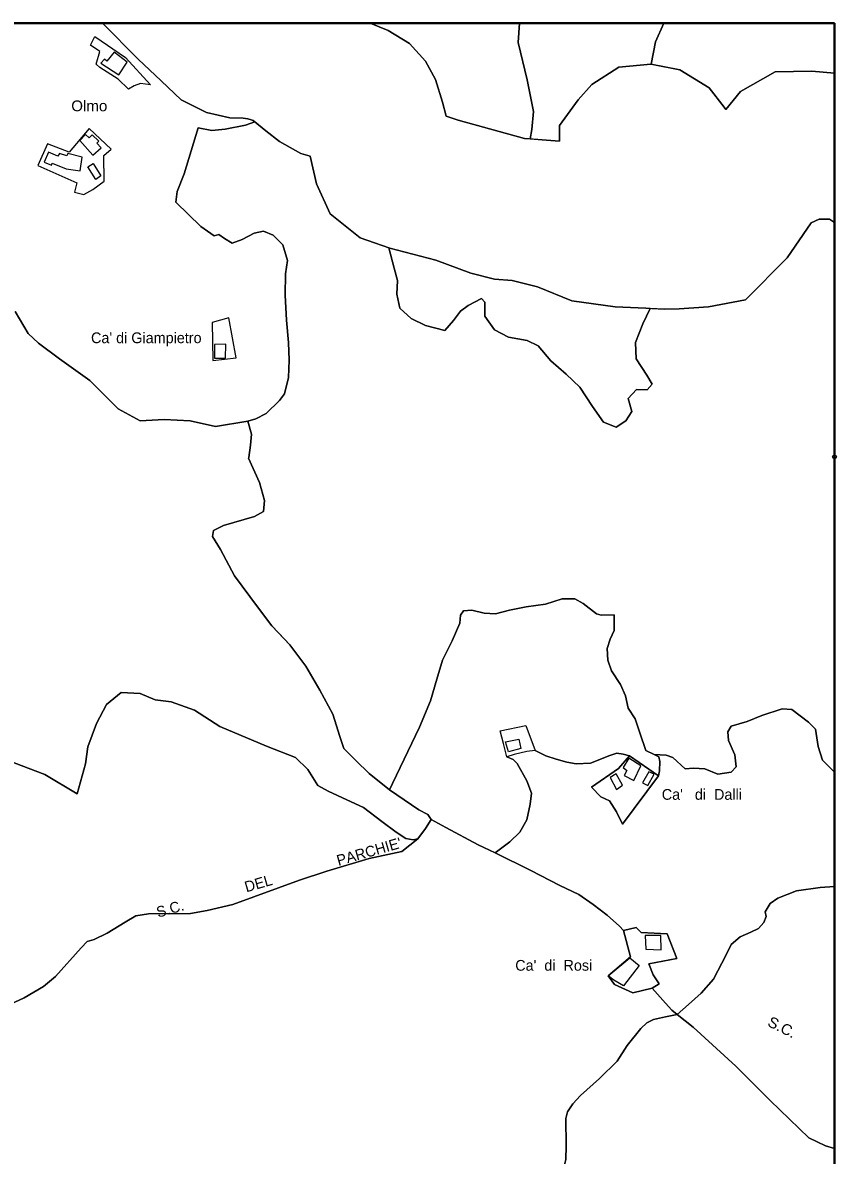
# Model space of a CAD drawing. Extents: x 650071 to 653841, y 889105 to 891996.
# Drawn here: x 653235 to 653841, y 891152 to 891996 of the extents above; entities that cross this region are included whole.
import ezdxf
from ezdxf.enums import TextEntityAlignment as Align

# ---------------------------------------------------------------- set-up
doc = ezdxf.new("R2010")
doc.units = 0
doc.header["$LTSCALE"] = 5.6
doc.header["$PDMODE"] = 32
doc.header["$PDSIZE"] = 2.8
for name, color, linetype, lineweight in [('2', 7, 'Continuous', 25), ('3', 7, 'Continuous', 25), ('36', 7, 'Continuous', 25), ('37', 7, 'Continuous', 25), ('4', 7, 'Continuous', 25), ('55', 7, 'Continuous', 25), ('61', 7, 'Continuous', 35)]:
    doc.layers.add(name, color=color, linetype=linetype, lineweight=lineweight)
doc.layers.add('60', color=7, linetype='Continuous')

msp = doc.modelspace()

# ---------------------------------------------------------------- linework, layer by layer
at = {"layer": '2'}
for points in [[(653330.45, 891949.72), (653322.99, 891950.77), (653318.29, 891949.07), (653314.09, 891946.47), (653306.31, 891953.92), (653292.79, 891962.67), (653290.09, 891965.17), (653292.79, 891974.67), (653285.68, 891979.43), (653289.08, 891985.9), (653311.75, 891970.13)], [(653296.11, 891968.89), (653293.5, 891965.94), (653306.88, 891957.2), (653313, 891966.62), (653303.36, 891974.1), (653298.04, 891967.41)], [(653253.81, 891905.82), (653246.6, 891889.79), (653275.59, 891876.74), (653273.87, 891869.94), (653280.67, 891868.22), (653287.44, 891871.96), (653295.82, 891878.11), (653295.61, 891897.11), (653301.13, 891902), (653284.79, 891917.28), (653269.94, 891899.66)], [(653277.82, 891908.39), (653287.49, 891897.46), (653293.63, 891902.88), (653290.52, 891906.38), (653292.02, 891907.88), (653286.97, 891912.52), (653284.65, 891910.33), (653282.06, 891912.79)], [(653254.37, 891899.55), (653251.37, 891892.18), (653256.61, 891889.88), (653257.19, 891891.34), (653267.71, 891887.14), (653278, 891885.65), (653279.49, 891895.94), (653268.83, 891898.73), (653268.01, 891896.82), (653262.6, 891898.74), (653261.47, 891896.55)], [(653283.7, 891888.77), (653287.79, 891891.09), (653293.38, 891882.04), (653289.7, 891879.22)]]:
    msp.add_lwpolyline(points, close=True, dxfattribs=at)
at = {"layer": '3'}
for points in [[(653682.6, 891319.93), (653687.83, 891300.33), (653671.37, 891286.21), (653676.04, 891279.79), (653689.53, 891273.61), (653703.92, 891277.04), (653709.26, 891280.11), (653704.85, 891286.88), (653701.65, 891295.12), (653722.31, 891299.02), (653715.14, 891317.55), (653695.92, 891318.37)], [(653695.92, 891318.37), (653692.01, 891322.29), (653682.6, 891319.93)]]:
    msp.add_lwpolyline(points, dxfattribs=at)
for points in [[(653698.85, 891316.3), (653699.41, 891306.08), (653710.76, 891305.52), (653710.55, 891316.28)], [(653687.3, 891299.55), (653694.35, 891293.8), (653682.6, 891278.64), (653675.55, 891283.08), (653671.37, 891286.21)]]:
    msp.add_lwpolyline(points, close=True, dxfattribs=at)
at = {"layer": '36'}
msp.add_line((653839.8, 891672.75), (653839.8, 891847.21), dxfattribs=at)
for points in [[(653635.09, 891907.74), (653635.09, 891919.48), (653648.99, 891938.74), (653659.02, 891950.02), (653679.3, 891962.85), (653703.06, 891965.22), (653703.36, 891965.16), (653706.62, 891981.91), (653712.77, 891995.66), (653605.2, 891995.66), (653604.37, 891981.36), (653610.85, 891953.6), (653615.71, 891930.03), (653614.41, 891916.49), (653613.09, 891909.5)], [(653486.68, 891835.79), (653464.3, 891853.71), (653454.16, 891876.01), (653449.23, 891896.62), (653442.41, 891898.73), (653426.57, 891907.6), (653416.27, 891915.57), (653408.04, 891922.15), (653401.11, 891919.7), (653386.07, 891916.68), (653376.21, 891915.68), (653365.84, 891917.69), (653355.47, 891883.48), (653350.29, 891870.39), (653349.25, 891862.34), (653367.92, 891844.23), (653377.75, 891837.41), (653381.38, 891838.42), (653385.53, 891835.4), (653391.29, 891831.94), (653398.82, 891834.59), (653407.56, 891839.27), (653414.48, 891840.9), (653421.83, 891837.91), (653429.04, 891830.75), (653432.57, 891818.88), (653430.97, 891808.93), (653430.65, 891793.14), (653431.68, 891774.52), (653433.24, 891757.92), (653433.76, 891744.83), (653433.24, 891731.75), (653430.13, 891719.68), (653426.5, 891714.65), (653416.65, 891705.09), (653408.87, 891701.06), (653402.99, 891699.2)], [(653613.09, 891909.5), (653622.15, 891908.91), (653635.09, 891907.74)], [(653839.8, 891847.21), (653836.07, 891849.78), (653828.33, 891849.8), (653822.45, 891846.94), (653804.61, 891820.85), (653773.64, 891789.59), (653746.05, 891784.44)], [(653746.05, 891784.44), (653724.27, 891782.85), (653712.92, 891782.78), (653702.45, 891783.21), (653697.11, 891771.88), (653691.73, 891757.95), (653692.23, 891745.82), (653700.17, 891733.6), (653704.12, 891726.81), (653700.21, 891722.54), (653692.43, 891723.01), (653686.12, 891716.29), (653688.98, 891706.52), (653684.5, 891699.59), (653677.17, 891694.91), (653667.88, 891698.58), (653659.58, 891710.15), (653650.24, 891724.74), (653639.93, 891734.42), (653628.46, 891744.36), (653619.13, 891755.43), (653610.99, 891759.31), (653596.99, 891761.82), (653586.62, 891767.36), (653579.36, 891777.42), (653579.36, 891787.98), (653577.06, 891790.6), (653566.91, 891785.47), (653561.19, 891781.24), (653556.02, 891774.4), (653549.59, 891766.78), (653535.14, 891770.65), (653524.56, 891775.74), (653516.22, 891783.48), (653513.98, 891793.86), (653514.39, 891804.04), (653511.94, 891813.21), (653507.87, 891828.28), (653507.86, 891828.35), (653486.68, 891835.79)], [(653415.46, 891640.27), (653411.72, 891653.73), (653403.5, 891671.68), (653403.59, 891672.24), (653405, 891681.4), (653405.75, 891689.62), (653402.99, 891699.2), (653378.9, 891695.4), (653359.98, 891699.6), (653340.51, 891700.65), (653322.67, 891699.6), (653306.46, 891708.51), (653285.37, 891729.49), (653262.67, 891745.75), (653246.99, 891757.28), (653239.42, 891764.63), (653229.69, 891780.88)], [(653402.99, 891699.2), (653405.75, 891689.62), (653405, 891681.4), (653403.59, 891672.24), (653403.5, 891671.68)], [(653728.68, 891440.33), (653734.9, 891440.84), (653743.2, 891440.33), (653753.05, 891436.31), (653762.91, 891437.82), (653766.49, 891441.82), (653765.5, 891450.9), (653760.83, 891461.47), (653760.31, 891468.01), (653762.91, 891472.03), (653774.83, 891475.55), (653785.72, 891480.08), (653800.76, 891485.11), (653808.02, 891484.61), (653820.47, 891475.05), (653825.65, 891470.02), (653827.73, 891456.94), (653830.84, 891446.88), (653839.8, 891437.91), (653839.8, 891672.75)], [(653403.5, 891671.68), (653411.72, 891653.73), (653415.46, 891640.27)], [(653407.99, 891628.31), (653414.71, 891632.05), (653415.46, 891640.27)], [(653415.46, 891640.27), (653414.71, 891632.05), (653407.99, 891628.31)], [(653407.99, 891628.31), (653384.82, 891621.58), (653377.35, 891617.84), (653376.6, 891613.35)], [(653377.35, 891617.84), (653384.82, 891621.58), (653407.99, 891628.31)], [(653410.23, 891561.01), (653393.04, 891584.19), (653382.58, 891603.63), (653376.6, 891613.35), (653377.35, 891617.84)], [(653376.6, 891613.35), (653382.58, 891603.63), (653393.04, 891584.19), (653410.23, 891561.01)], [(653474.49, 891455.58), (653483.45, 891446.61), (653493.17, 891436.89), (653508.52, 891424.77), (653510.59, 891429.39), (653530.78, 891471.39), (653539.08, 891491.01), (653543.75, 891507.11), (653547.9, 891521.2), (653555.16, 891535.79), (653560.86, 891548.87), (653561.38, 891554.91), (653563.45, 891557.93), (653569.68, 891558.43), (653579.01, 891556.42), (653587.31, 891555.92), (653597.68, 891558.43), (653610.12, 891560.95), (653624.64, 891562.96), (653637.09, 891566.99), (653646.42, 891566.99), (653652.65, 891563.47), (653662.5, 891555.92), (653666.13, 891554.91), (653675.79, 891555.05), (653675.79, 891543.48), (653672.68, 891536.94), (653670.6, 891529.89), (653671.12, 891521.34), (653673.71, 891513.29), (653680.45, 891503.23), (653684.08, 891494.67), (653686.16, 891485.62), (653691.34, 891477.57), (653694.86, 891467.21), (653699.34, 891454.02), (653705.56, 891451.03), (653714.51, 891450.53), (653719.35, 891448.89), (653728.68, 891440.33)], [(653446.09, 891516.9), (653434.14, 891532.6), (653420.69, 891546.81), (653410.23, 891561.01)], [(653410.23, 891561.01), (653420.69, 891546.81), (653430.38, 891536.57)], [(653430.38, 891536.57), (653434.14, 891532.6), (653446.09, 891516.9), (653456.55, 891498.95), (653466.27, 891481.01), (653471.5, 891464.56), (653474.49, 891455.58)], [(653466.27, 891481.01), (653456.55, 891498.95), (653446.09, 891516.9)], [(653218.3, 891448.84), (653251.82, 891436.25), (653275.87, 891421.67), (653282.09, 891444.13), (653283.71, 891456.71), (653290.2, 891474.02), (653297.77, 891488.18), (653308.58, 891497.09), (653322.64, 891496.57), (653333.99, 891491.85), (653345.89, 891490.28), (653363.19, 891483.98), (653382.11, 891471.92), (653416.71, 891457.24), (653438.34, 891448.85), (653447.53, 891439.93), (653455.09, 891427.87), (653462.66, 891423.67), (653476.72, 891417.38), (653489.15, 891411.61), (653502.67, 891401.12), (653513.48, 891393.25), (653520.51, 891388.53), (653526.16, 891387.38), (653529.61, 891388.13), (653535.33, 891396), (653539.36, 891402.53), (653536.86, 891406.42), (653530.33, 891409.76), (653508.52, 891424.77)], [(653474.49, 891455.58), (653471.5, 891464.56), (653466.27, 891481.01)], [(653508.52, 891424.77), (653493.17, 891436.89), (653483.45, 891446.61), (653474.49, 891455.58)]]:
    msp.add_lwpolyline(points, dxfattribs=at)
msp.add_lwpolyline([(653766.24, 891218.93), (653791.87, 891193.27), (653820.79, 891165.63), (653833.1, 891159.64), (653839.8, 891157.64), (653839.8, 891352.62), (653829.27, 891352.02), (653811.64, 891349.5), (653797.63, 891343.97), (653791.93, 891339.94), (653788.3, 891333.9), (653788.82, 891330.38), (653787.26, 891325.85), (653783.11, 891321.33), (653777.41, 891318.81), (653769.63, 891315.29), (653762.79, 891309.47), (653759.16, 891301.92), (653749.83, 891283.81), (653740.49, 891273.24), (653730.98, 891264.89), (653722.68, 891257.28), (653734.69, 891247.89)], close=True, dxfattribs=at)
msp.add_point((653839.8, 891672.75), dxfattribs=at)
at = {"layer": '37'}
msp.add_line((653714.51, 891450.53), (653705.56, 891451.03), dxfattribs=at)
for points in [[(653294.78, 891995.66), (653294.8, 891995.96), (653024.92, 891996.11)], [(653408.04, 891922.15), (653406.81, 891923.13), (653405.32, 891923.78), (653402.91, 891924.4), (653399.55, 891924.9), (653389.62, 891925.3), (653372.19, 891929.26), (653353.27, 891938.72), (653338.29, 891952.71), (653321.16, 891968.83), (653294.78, 891995.66)], [(653608.88, 891909.77), (653613.09, 891909.5), (653614.41, 891916.49), (653615.71, 891930.03), (653610.85, 891953.6), (653604.37, 891981.36), (653605.2, 891995.66), (653494, 891995.66)], [(653494, 891995.66), (653507.54, 891990.37), (653523.21, 891980.49), (653535.35, 891967.48), (653542.65, 891953.68), (653547.94, 891936.81), (653550.75, 891926.57), (653559.65, 891923.44), (653608.88, 891909.77)], [(653839.8, 891958.58), (653839.81, 891995.66), (653712.77, 891995.66), (653706.62, 891981.91), (653703.36, 891965.16)], [(653703.36, 891965.16), (653724.73, 891960.89), (653746.57, 891947.62)], [(653746.57, 891947.62), (653757.69, 891933.22), (653758.82, 891931.41), (653769.72, 891944.73), (653795.71, 891959.47), (653823.03, 891959.98), (653839.8, 891958.58)], [(653350.29, 891870.39), (653355.47, 891883.48), (653365.84, 891917.69), (653376.21, 891915.68), (653386.07, 891916.68), (653401.11, 891919.7), (653408.04, 891922.15)], [(653229.69, 891780.88), (653239.42, 891764.63), (653246.99, 891757.28), (653262.67, 891745.75), (653285.37, 891729.49), (653306.46, 891708.51), (653322.67, 891699.6), (653340.51, 891700.65), (653359.98, 891699.6), (653378.9, 891695.4), (653402.99, 891699.2), (653408.87, 891701.06), (653416.65, 891705.09), (653426.5, 891714.65), (653430.13, 891719.68), (653433.24, 891731.75), (653433.76, 891744.83), (653433.24, 891757.92), (653431.68, 891774.52), (653430.65, 891793.14), (653430.97, 891808.93), (653432.57, 891818.88), (653429.04, 891830.75), (653421.83, 891837.91), (653414.48, 891840.9), (653407.56, 891839.27), (653398.82, 891834.59), (653391.29, 891831.94), (653385.53, 891835.4), (653381.38, 891838.42), (653377.75, 891837.41), (653367.92, 891844.23), (653349.25, 891862.34), (653350.29, 891870.39)], [(653507.87, 891828.28), (653511.94, 891813.21), (653514.39, 891804.04), (653513.98, 891793.86), (653516.22, 891783.48), (653524.56, 891775.74), (653535.14, 891770.65), (653549.59, 891766.78), (653556.02, 891774.4), (653561.19, 891781.24), (653566.91, 891785.47), (653577.06, 891790.6), (653579.36, 891787.98), (653579.36, 891777.42), (653586.62, 891767.36), (653596.99, 891761.82), (653610.99, 891759.31), (653619.13, 891755.43), (653628.46, 891744.36), (653639.93, 891734.42), (653650.24, 891724.74)], [(653599.77, 891804), (653586.63, 891804.97), (653569.03, 891809.63), (653542.86, 891819.2), (653508.56, 891828.1), (653507.89, 891828.34)], [(653702.45, 891783.21), (653699.3, 891783.35), (653676.6, 891784.48), (653644.25, 891789.02), (653618.72, 891799.25), (653599.77, 891804)], [(653650.24, 891724.74), (653659.58, 891710.15), (653667.88, 891698.58), (653677.17, 891694.91), (653684.5, 891699.59), (653688.98, 891706.52), (653686.12, 891716.29), (653692.43, 891723.01), (653700.21, 891722.54), (653704.12, 891726.81), (653700.17, 891733.6), (653692.23, 891745.82), (653691.73, 891757.95), (653697.11, 891771.88), (653702.45, 891783.21)], [(653708.81, 891435.22), (653709.6, 891438.85), (653709.82, 891445.85), (653708.95, 891449.35), (653705.56, 891451.03), (653699.34, 891454.02), (653694.86, 891467.21), (653691.34, 891477.57), (653686.16, 891485.62), (653684.08, 891494.67), (653680.45, 891503.23), (653673.71, 891513.29), (653671.12, 891521.34), (653670.6, 891529.89), (653672.68, 891536.94), (653675.79, 891543.48), (653675.79, 891555.05), (653666.13, 891554.91), (653662.5, 891555.92), (653652.65, 891563.47), (653646.42, 891566.99), (653637.09, 891566.99), (653624.64, 891562.96), (653610.12, 891560.95), (653597.68, 891558.43), (653587.31, 891555.92), (653579.01, 891556.42), (653569.68, 891558.43), (653563.45, 891557.93), (653561.38, 891554.91), (653560.86, 891548.87), (653555.16, 891535.79), (653547.9, 891521.2), (653543.75, 891507.11), (653539.08, 891491.01), (653530.78, 891471.39), (653510.59, 891429.39), (653508.52, 891424.77), (653530.33, 891409.76)], [(653278.74, 891306.98), (653283.17, 891311.85), (653288.49, 891313.18), (653298.24, 891318.06), (653311.54, 891326.05), (653319.52, 891330.92), (653328.83, 891332.25), (653360.29, 891332.7), (653372.7, 891334.92), (653391.76, 891339.35), (653441.41, 891357.53), (653461.8, 891364.18), (653493.27, 891373.49), (653517.64, 891378.82), (653529.61, 891388.13), (653526.16, 891387.38), (653520.51, 891388.53), (653513.48, 891393.25), (653502.67, 891401.12), (653489.15, 891411.61), (653476.72, 891417.38), (653462.66, 891423.67), (653455.09, 891427.87), (653447.53, 891439.93), (653438.34, 891448.85), (653416.71, 891457.24), (653382.11, 891471.92), (653363.19, 891483.98), (653345.89, 891490.28), (653333.99, 891491.85), (653322.64, 891496.57), (653308.58, 891497.09), (653297.77, 891488.18), (653290.2, 891474.02), (653283.71, 891456.71), (653282.09, 891444.13), (653275.87, 891421.67), (653251.82, 891436.25), (653218.3, 891448.84)], [(653714.05, 891265.78), (653718.73, 891260.67), (653722.68, 891257.28), (653730.98, 891264.89), (653740.49, 891273.24), (653749.83, 891283.81), (653759.16, 891301.92), (653762.79, 891309.47), (653769.63, 891315.29), (653777.41, 891318.81), (653783.11, 891321.33), (653787.26, 891325.85), (653788.82, 891330.38), (653788.3, 891333.9), (653791.93, 891339.94), (653797.63, 891343.97), (653811.64, 891349.5), (653829.27, 891352.02), (653839.8, 891352.62), (653839.8, 891437.91), (653830.84, 891446.88), (653827.73, 891456.94), (653825.65, 891470.02), (653820.47, 891475.05), (653808.02, 891484.61), (653800.76, 891485.11), (653785.72, 891480.08), (653774.83, 891475.55), (653762.91, 891472.03), (653760.31, 891468.01), (653760.83, 891461.47), (653765.5, 891450.9), (653766.49, 891441.82), (653762.91, 891437.82), (653753.05, 891436.31), (653743.2, 891440.33), (653734.9, 891440.84), (653728.68, 891440.33), (653719.35, 891448.89), (653714.51, 891450.53)], [(653550.35, 891396.72), (653574.46, 891383.67), (653587.17, 891377.81), (653597.92, 891385.96), (653605.42, 891393.13), (653610.63, 891402.26), (653613.24, 891414), (653614.22, 891422.15), (653610.59, 891431.41), (653603.46, 891444.32), (653600.53, 891447.26), (653595.74, 891449.31), (653593.25, 891459.32), (653590.91, 891468.62), (653609.87, 891472.52), (653616.79, 891454.05)], [(653687.27, 891450.1), (653682.42, 891451.3), (653677.82, 891452.1), (653672.61, 891450.3), (653658.2, 891444.49), (653647.39, 891444.09), (653640.58, 891445.29), (653632.57, 891447.49), (653624.97, 891450.1), (653616.79, 891454.05), (653610.79, 891453.25), (653601.38, 891451.05), (653595.74, 891449.31)], [(653616.79, 891454.05), (653624.97, 891450.1), (653632.57, 891447.49), (653640.58, 891445.29), (653647.39, 891444.09), (653658.2, 891444.49), (653672.61, 891450.3), (653677.82, 891452.1), (653682.42, 891451.3), (653687.27, 891450.1), (653708.81, 891435.22)], [(653595.74, 891449.31), (653600.53, 891447.26), (653603.46, 891444.32), (653610.59, 891431.41), (653614.22, 891422.15), (653613.24, 891414), (653610.63, 891402.26), (653605.42, 891393.13), (653597.92, 891385.96), (653587.17, 891377.81)], [(653705.56, 891451.03), (653708.95, 891449.35), (653709.82, 891445.85), (653709.6, 891438.85), (653708.81, 891435.22), (653682.05, 891399.12), (653677.42, 891408.28), (653672.15, 891416.42), (653665.85, 891419.42), (653658.94, 891426.78), (653678.96, 891440.61), (653687.27, 891450.1)], [(653530.33, 891409.76), (653536.86, 891406.42), (653539.36, 891402.53), (653550.35, 891396.72)], [(653587.17, 891377.81), (653574.46, 891383.67), (653550.35, 891396.72), (653539.36, 891402.53), (653535.33, 891396), (653529.61, 891388.13)], [(653529.61, 891388.13), (653517.64, 891378.82), (653493.27, 891373.49), (653461.8, 891364.18), (653441.41, 891357.53), (653391.76, 891339.35), (653372.7, 891334.92), (653360.29, 891332.7), (653328.83, 891332.25), (653319.52, 891330.92), (653311.54, 891326.05), (653298.24, 891318.06), (653288.49, 891313.18), (653283.17, 891311.85), (653278.74, 891306.98)], [(653682.6, 891319.93), (653679.59, 891323.26), (653670.65, 891331.35), (653660.01, 891339.44), (653649.37, 891346.67), (653635.33, 891353.49), (653613.63, 891364.56), (653587.17, 891377.81)], [(653587.17, 891377.81), (653613.63, 891364.56), (653635.33, 891353.49), (653649.37, 891346.67), (653660.01, 891339.44)], [(653660.01, 891339.44), (653670.65, 891331.35), (653679.59, 891323.26), (653682.6, 891319.93)], [(653722.68, 891257.28), (653718.73, 891260.67), (653714.05, 891265.78), (653703.92, 891277.04), (653689.53, 891273.61), (653676.04, 891279.79), (653671.37, 891286.21), (653687.83, 891300.33), (653682.6, 891319.93)], [(653682.6, 891319.93), (653692.01, 891322.29), (653695.92, 891318.37), (653715.14, 891317.55), (653722.31, 891299.02), (653701.65, 891295.12), (653704.85, 891286.88), (653709.26, 891280.11), (653703.92, 891277.04), (653714.05, 891265.78)], [(653157.88, 891259.31), (653169.6, 891257.3), (653184.23, 891254.64), (653195.31, 891255.3), (653216.37, 891260.63), (653236.31, 891269.72), (653250.82, 891278.15), (653259.68, 891285.69), (653278.74, 891306.98)], [(653278.74, 891306.98), (653259.68, 891285.69), (653250.82, 891278.15), (653236.31, 891269.72), (653216.37, 891260.63), (653195.31, 891255.3), (653184.23, 891254.64), (653169.6, 891257.3), (653157.88, 891259.31)], [(653615.64, 891028.21), (653620.37, 891038.42), (653625.8, 891060.14), (653629.32, 891070.73), (653632.85, 891093.26), (653636.1, 891135.87), (653638, 891142.39), (653639.63, 891149.45), (653639.9, 891159.49), (653639.63, 891179.85), (653640.99, 891185), (653645.06, 891190.98), (653650.75, 891196.95), (653664.86, 891209.71), (653677.88, 891222.73), (653685.48, 891234.41), (653695.52, 891246.89), (653700.13, 891251.24), (653705.01, 891253.68), (653713.97, 891255.58), (653722.68, 891257.28)], [(653722.68, 891257.28), (653713.97, 891255.58), (653705.01, 891253.68), (653700.13, 891251.24), (653695.52, 891246.89), (653685.48, 891234.41), (653677.88, 891222.73), (653664.86, 891209.71), (653650.75, 891196.95), (653645.06, 891190.98), (653640.99, 891185), (653639.63, 891179.85), (653639.9, 891159.49), (653639.63, 891149.45), (653638, 891142.39), (653636.1, 891135.87), (653632.85, 891093.26), (653629.32, 891070.73), (653625.8, 891060.14), (653620.37, 891038.42), (653615.64, 891028.21), (653632.33, 891016)], [(653722.42, 890725.73), (653769.83, 890705.74), (653784.77, 890700.24), (653805.38, 890694.24), (653825.99, 890690.24), (653835.75, 890691.19), (653839.8, 890691.58), (653839.8, 891157.64), (653833.1, 891159.64), (653820.79, 891165.63), (653791.87, 891193.27), (653766.24, 891218.93), (653734.69, 891247.89), (653722.68, 891257.28)]]:
    msp.add_lwpolyline(points, dxfattribs=at)
at = {"layer": '4'}
for points in [[(653376.35, 891772.68), (653376.81, 891744.52), (653394.34, 891746.36), (653388.8, 891776.37)], [(653378.21, 891756.36), (653378.21, 891746.17), (653386.4, 891746.27), (653386.51, 891756.65)], [(653601.38, 891451.05), (653595.74, 891449.31), (653593.25, 891459.32), (653590.91, 891468.62), (653609.87, 891472.52), (653616.79, 891454.05), (653610.79, 891453.25)], [(653594.8, 891460.44), (653604.82, 891462.54), (653606.29, 891455.5), (653596.99, 891452.91)], [(653672.15, 891416.42), (653677.42, 891408.28), (653682.05, 891399.12), (653708.81, 891435.22), (653687.27, 891450.1), (653678.96, 891440.61), (653658.94, 891426.78), (653665.85, 891419.42)], [(653682.49, 891441.38), (653685.16, 891439.09), (653683.17, 891435.34), (653690.33, 891431.72), (653695.7, 891442.6), (653686.65, 891448.2)], [(653672.64, 891433.82), (653677.48, 891425.02), (653682, 891428.31), (653677.24, 891436.61)], [(653701.44, 891438.15), (653696.87, 891429.95), (653700.73, 891427.84), (653705.42, 891436.28)], [(653701.44, 891438.15), (653696.87, 891429.95), (653700.73, 891427.84), (653705.42, 891436.28)]]:
    msp.add_lwpolyline(points, close=True, dxfattribs=at)
at = {"layer": '55'}
for points in [[(653839.8, 891958.58), (653823.03, 891959.98), (653795.71, 891959.47), (653769.72, 891944.73), (653758.82, 891931.41), (653757.69, 891933.22), (653746.57, 891947.62), (653724.73, 891960.89), (653703.06, 891965.22), (653679.3, 891962.85), (653659.02, 891950.02), (653648.99, 891938.74), (653635.09, 891919.48), (653635.09, 891907.74), (653622.15, 891908.91), (653608.88, 891909.77), (653559.65, 891923.44), (653550.75, 891926.57), (653547.94, 891936.81), (653542.65, 891953.68), (653535.35, 891967.48), (653523.21, 891980.49), (653507.54, 891990.37), (653494, 891995.66), (653294.78, 891995.66), (653321.16, 891968.83)], [(653321.16, 891968.83), (653338.29, 891952.71), (653353.27, 891938.72), (653372.19, 891929.26), (653389.62, 891925.3), (653399.55, 891924.9), (653402.91, 891924.4), (653405.32, 891923.78), (653406.81, 891923.13), (653416.27, 891915.57), (653426.57, 891907.6), (653442.41, 891898.73), (653449.23, 891896.62), (653454.16, 891876.01), (653464.3, 891853.71), (653486.68, 891835.79), (653508.56, 891828.1), (653542.86, 891819.2), (653569.03, 891809.63), (653586.63, 891804.97), (653599.77, 891804)], [(653712.92, 891782.78), (653724.27, 891782.85), (653746.05, 891784.44), (653773.64, 891789.59), (653804.61, 891820.85), (653822.45, 891846.94), (653828.33, 891849.8), (653836.07, 891849.78), (653839.8, 891847.21), (653839.8, 891958.58)], [(653599.77, 891804), (653618.72, 891799.25), (653644.25, 891789.02), (653676.6, 891784.48), (653699.3, 891783.35), (653712.92, 891782.78)]]:
    msp.add_lwpolyline(points, dxfattribs=at)
at = {"layer": '61', "lineweight": 40}
msp.add_lwpolyline([(653839.81, 891995.66), (653839.8, 889106.04), (652174.44, 889106.04), (652174.45, 891995.66)], close=True, dxfattribs=at)

# ---------------------------------------------------------------- texts
at = {"layer": '60', "width": 1.05}
msp.add_text('Olmo', height=8, dxfattribs=at).set_placement((653284.85, 891930.14), align=Align.CENTER)
at = {"layer": '60'}
for s, p in [("Ca' di Giampietro", (653327.31, 891757.39)), ("Ca'   di  Dalli", (653741.06, 891417.31)), ("Ca'  di  Rosi", (653630.74, 891290))]:
    msp.add_text(s, height=8, dxfattribs=at).set_placement(p, align=Align.CENTER)
msp.add_text("S.C.                DEL                 PARCHIE'", height=8, rotation=16.02, dxfattribs=at).set_placement((653427.11, 891355.59), align=Align.CENTER)
at = {"layer": '60', "width": 1.05}
msp.add_text('S.C.', height=8, rotation=333.419, dxfattribs=at).set_placement((653798.99, 891244.36), align=Align.CENTER)

doc.saveas('drawing.dxf')
